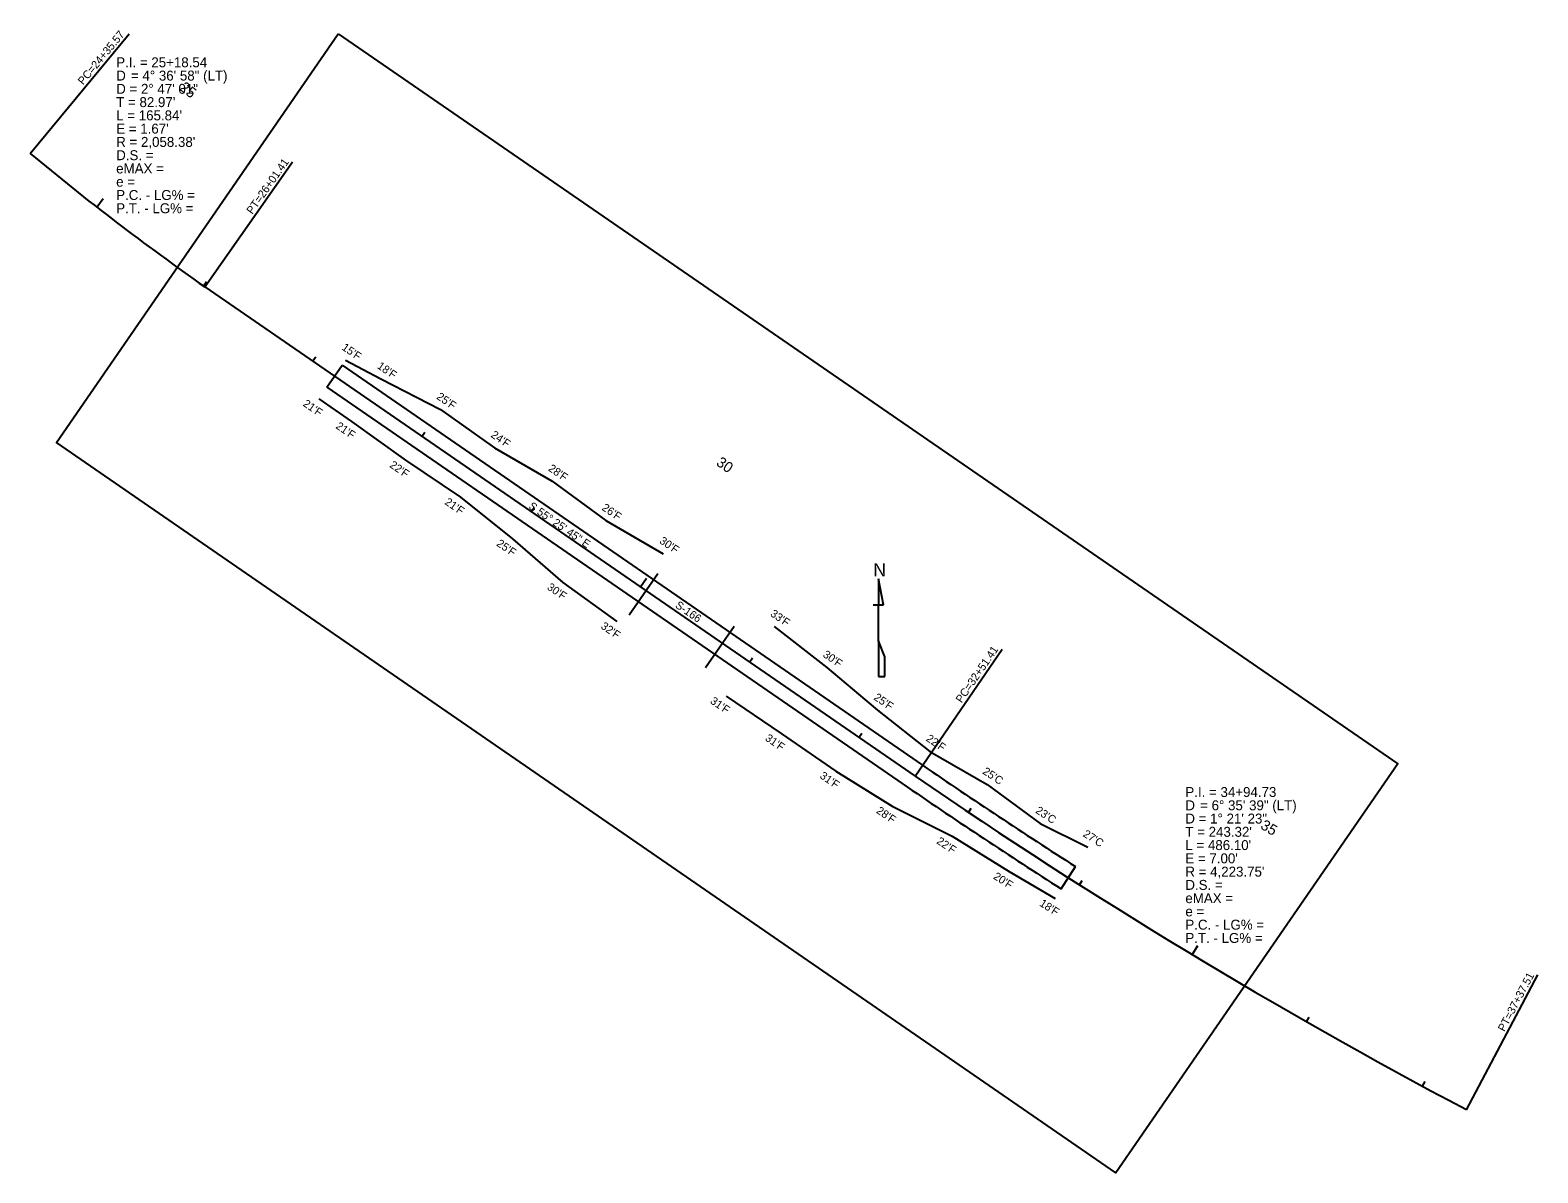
# Model space of a CAD drawing. Extents: x 1690070 to 1696783, y 823417 to 829859.
# Drawn here: x 1690070 to 1691207, y 828998 to 829859 of the extents above; entities that cross this region are included whole.
import ezdxf

# ---------------------------------------------------------------- set-up
doc = ezdxf.new("R2010")
doc.units = 0
for name, color, linetype in [('GN_Clip', 7, 'Continuous'), ('RD_EX_Misc', 7, 'Continuous'), ('RD_HC_Cl', 7, 'Continuous'), ('RD_HC_Data', 7, 'Continuous'), ('RD_HC_Data_Tic', 7, 'Continuous'), ('RD_HC_TX_Sta50', 7, 'Continuous'), ('RD_PD_Bridge', 7, 'Continuous'), ('RD_PD_CstnLmt', 7, 'Continuous'), ('RD_PD_CstnLmt_TX', 7, 'Continuous'), ('RD_PD_Final_TrvlWay', 7, 'Continuous'), ('RD_TX_RoadID', 7, 'Continuous')]:
    doc.layers.add(name, color=color, linetype=linetype)

msp = doc.modelspace()

# ---------------------------------------------------------------- linework, layer by layer
at = {"layer": 'GN_Clip'}
msp.add_lwpolyline([(1690302.4, 829856.3), (1691101.1, 829305.9), (1690888.7, 828997.7), (1690090, 829548.1)], close=True, dxfattribs=at)
at = {"layer": 'RD_EX_Misc'}
for p, q in [((1690713.5, 829425.8), (1690709.6, 829445.4)), ((1690709.6, 829445.4), (1690709.6, 829445.4)), ((1690709.6, 829445.4), (1690709.6, 829425.8)), ((1690705.7, 829425.8), (1690709.6, 829425.8)), ((1690709.6, 829398.6), (1690709.6, 829425.8)), ((1690709.6, 829425.8), (1690713.5, 829425.8)), ((1690713.5, 829425.8), (1690713.5, 829426)), ((1690714.5, 829386.6), (1690709.6, 829398.6)), ((1690709.6, 829398.6), (1690709.6, 829371.9)), ((1690714.5, 829371.9), (1690714.5, 829386.7)), ((1690714.5, 829386.7), (1690714.5, 829386.6)), ((1690709.6, 829371.9), (1690714.5, 829371.9))]:
    msp.add_line(p, q, dxfattribs=at)
at = {"layer": 'RD_HC_Cl'}
msp.add_line((1690201.9, 829665.5), (1690737.2, 829296.6), dxfattribs=at)
for centre, radius, start, end in [((1691383.5, 831350.9), 2058.4, 230.3516, 234.9678), ((1693126.7, 832779.5), 4223.7, 235.5468, 242.1408)]:
    msp.add_arc(centre, radius, start, end, dxfattribs=at)
at = {"layer": 'RD_HC_Data'}
for p, q in [((1690070.1, 829766), (1690144.7, 829856.1)), ((1690201.9, 829665.5), (1690268, 829759.7)), ((1690737.2, 829296.6), (1690802.8, 829392.3)), ((1691152.9, 829045.3), (1691206.7, 829147))]:
    msp.add_line(p, q, dxfattribs=at)
at = {"layer": 'RD_HC_Data_Tic'}
for p, q in [((1690120.4, 829725.7), (1690125.3, 829732)), ((1690200.8, 829666.3), (1690203.1, 829669.5)), ((1690283.1, 829609.5), (1690285.4, 829612.8)), ((1690365.5, 829552.8), (1690367.7, 829556.1)), ((1690447.8, 829496), (1690450.1, 829499.3)), ((1690530.2, 829439.3), (1690534.7, 829445.9)), ((1690612.5, 829382.5), (1690614.8, 829385.8)), ((1690694.8, 829325.8), (1690697.1, 829329.1)), ((1690777.4, 829269.4), (1690779.6, 829272.7)), ((1690861.2, 829214.7), (1690863.3, 829218.1)), ((1690946.2, 829162.1), (1690950.3, 829169)), ((1691032.4, 829111.5), (1691034.4, 829115)), ((1691119.8, 829063), (1691121.7, 829066.5))]:
    msp.add_line(p, q, dxfattribs=at)
at = {"layer": 'RD_PD_Bridge'}
for p, q in [((1690521.6, 829418.3), (1690543.2, 829449.5)), ((1690579.3, 829378.6), (1690600.8, 829409.8))]:
    msp.add_line(p, q, dxfattribs=at)
at = {"layer": 'RD_PD_CstnLmt'}
for p, q in [((1690307.9, 829610.2), (1690334.6, 829596.2)), ((1690334.6, 829596.2), (1690379.4, 829573.1)), ((1690287.8, 829581), (1690312.5, 829564)), ((1690312.5, 829564), (1690353.1, 829534.8)), ((1690379.4, 829573.1), (1690420.3, 829544.2)), ((1690420.3, 829544.2), (1690463.6, 829519)), ((1690353.1, 829534.8), (1690394.6, 829506.9)), ((1690463.6, 829519), (1690504, 829489.4)), ((1690394.6, 829506.9), (1690433.7, 829475.6)), ((1690504, 829489.4), (1690547.4, 829464.4)), ((1690433.7, 829475.6), (1690471.8, 829442.7)), ((1690471.8, 829442.7), (1690512.3, 829413.3)), ((1690631, 829409.4), (1690670.6, 829378.7)), ((1690670.6, 829378.7), (1690709, 829346.4)), ((1690594.8, 829356.9), (1690636.2, 829328.9)), ((1690709, 829346.4), (1690748.4, 829315.4)), ((1690636.2, 829328.9), (1690677.4, 829300.5)), ((1690748.4, 829315.4), (1690791.5, 829290.4)), ((1690677.4, 829300.5), (1690720, 829274.1)), ((1690791.5, 829290.4), (1690831.5, 829260.9)), ((1690720, 829274.1), (1690765.3, 829251.4)), ((1690831.5, 829260.9), (1690867.4, 829243.1)), ((1690765.3, 829251.4), (1690808.1, 829224.9)), ((1690808.1, 829224.9), (1690842.8, 829204.5))]:
    msp.add_line(p, q, dxfattribs=at)
at = {"layer": 'RD_PD_Final_TrvlWay'}
for p, q in [((1690293.9, 829589.9), (1690305.3, 829606.4)), ((1690305.3, 829606.4), (1690742.9, 829304.9)), ((1690293.9, 829589.9), (1690731.5, 829288.4)), ((1690847.4, 829211.7), (1690858.1, 829228.6))]:
    msp.add_line(p, q, dxfattribs=at)
for radius, end in [(4213.7, 237.4264), (4233.7, 237.4271)]:
    msp.add_arc((1693126.7, 832779.5), radius, 235.5468, end, dxfattribs=at)

# ---------------------------------------------------------------- texts
at = {"layer": 'RD_EX_Misc'}
msp.add_text('N', height=10, dxfattribs=at).set_placement((1690705.7, 829447.2))
at = {"layer": 'RD_HC_Data'}
for s, rotation, p in [('PC=24+35.57', 50.3516, (1690110.1, 829817.3)), ('PT=26+01.41', 54.9678, (1690237.6, 829719.8)), ('S 55%%d 25\' 45" E', 325.4291, (1690445.4, 829498.9)), ('PC=32+51.41', 55.5468, (1690772.3, 829351.4)), ('PT=37+37.51', 62.1408, (1691181.5, 829103.7))]:
    msp.add_text(s, height=6, rotation=rotation, dxfattribs=at).set_placement(p)
for s, p in [('P.I. = 25+18.54', (1690135, 829831)), ('D', (1690135, 829821)), ('    = 4%%d 36\' 58" (LT)', (1690135, 829821)), ('D = 2%%d 47\' 01"', (1690135, 829811)), ("T = 82.97'", (1690135, 829801)), ("L = 165.84'", (1690135, 829791)), ("E = 1.67'", (1690135, 829781)), ("R = 2,058.38'", (1690135, 829771)), ('D.S. = ', (1690135, 829761)), ('eMAX = ', (1690135, 829751)), ('e = ', (1690135, 829741)), ('P.C. - LG% = ', (1690135, 829731)), ('P.T. - LG% = ', (1690135, 829721)), ('P.I. = 34+94.73', (1690941, 829281)), ('D', (1690941, 829271)), ('D = 1%%d 21\' 23"', (1690941, 829261)), ('    = 6%%d 35\' 39" (LT)', (1690941, 829271)), ("T = 243.32'", (1690941, 829251)), ("L = 486.10'", (1690941, 829241)), ("E = 7.00'", (1690941, 829231)), ("R = 4,223.75'", (1690941, 829221)), ('D.S. = ', (1690941, 829211)), ('eMAX = ', (1690941, 829201)), ('e = ', (1690941, 829191)), ('P.C. - LG% = ', (1690941, 829181)), ('P.T. - LG% = ', (1690941, 829171))]:
    msp.add_text(s, height=7.5, dxfattribs=at).set_placement(p)
at = {"layer": 'RD_HC_TX_Sta50'}
for s, rotation, p in [('25', 322.145, (1690182.1, 829814.5)), ('30', 325.4291, (1690586.7, 829531.5)), ('35', 328.9189, (1690997, 829257.6))]:
    msp.add_text(s, height=8, rotation=rotation, dxfattribs=at).set_placement(p)
at = {"layer": 'RD_PD_CstnLmt_TX'}
for s, rotation, p in [("15'F", 325.4291, (1690304.5, 829618.6)), ("18'F", 325.4291, (1690331.2, 829604.6)), ("21'F", 325.4291, (1690275.3, 829576.2)), ("25'F", 325.4291, (1690376, 829581.5)), ("21'F", 325.4291, (1690300, 829559.3)), ("24'F", 325.4291, (1690416.9, 829552.7)), ("22'F", 325.4291, (1690340.6, 829530)), ("28'F", 325.4291, (1690460.2, 829527.4)), ("21'F", 325.4291, (1690382.1, 829502.1)), ("26'F", 325.4291, (1690500.6, 829497.8)), ("25'F", 325.4291, (1690421.2, 829470.8)), ("30'F", 325.4291, (1690544, 829472.8)), ("30'F", 325.4291, (1690459.3, 829437.9)), ("33'F", 325.4291, (1690627.6, 829417.9)), ("32'F", 325.4291, (1690499.8, 829408.5)), ("30'F", 325.4291, (1690667.2, 829387.1)), ("31'F", 325.4291, (1690582.3, 829352.1)), ("25'F", 325.4291, (1690705.6, 829354.8)), ("31'F", 325.4291, (1690623.7, 829324.1)), ("22'F", 325.4291, (1690745, 829323.8)), ("25'C", 326.2059, (1690787.6, 829299)), ("31'F", 325.4291, (1690664.9, 829295.7)), ("28'F", 325.4291, (1690707.5, 829269.4)), ("23'C", 326.8842, (1690827.5, 829269.4)), ("22'F", 326.2059, (1690752.9, 829246.4)), ("27'C", 327.4268, (1690863.3, 829251.7)), ("20'F", 326.8842, (1690795.7, 829219.8)), ("18'F", 327.4268, (1690830.5, 829199.4))]:
    msp.add_text(s, height=6, rotation=rotation, dxfattribs=at).set_placement(p)
at = {"layer": 'RD_TX_RoadID'}
msp.add_text('S-166', height=6, rotation=325.4291, dxfattribs=at).set_placement((1690555.9, 829424.3))

doc.saveas('drawing.dxf')
